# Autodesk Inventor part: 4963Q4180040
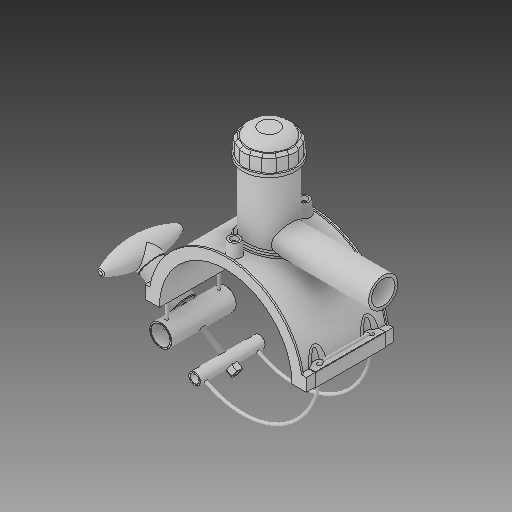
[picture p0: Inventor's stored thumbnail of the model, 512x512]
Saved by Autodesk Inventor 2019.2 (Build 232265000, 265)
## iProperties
Created: 2017-07
Part Number: 4963Q4180040
Material: Generic
Description: PLASSON TAPPING SADDLE 180x40
Document SubType Name: Modeling
Designer: KIM
Mass: 1712.7 g
Surface Area: 2671.49 cm^2
Volume: 1712.7 cm^3
Density: 1 g/cm^3
Appearance: Default
Author: KIM
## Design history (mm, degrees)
derived "4963Q4 (new clamping).ipt"
feature "Solid1::4963Q4 (new clamping).ipt"
feature "Solid2::4963Q4 (new clamping).ipt"
feature "Solid4::4963Q4 (new clamping).ipt"
feature "Solid5::4963Q4 (new clamping).ipt"
feature "Solid6::4963Q4 (new clamping).ipt"
feature "Solid7::4963Q4 (new clamping).ipt"
feature "Solid8::4963Q4 (new clamping).ipt"
feature "Solid9::4963Q4 (new clamping).ipt" dims "d70" = 15
feature "Solid10::4963Q4 (new clamping).ipt"
tag "TaggingFeature1"
body "Solid1"
body "Solid2"
body "Solid3"
body "Solid4"
body "Solid5"
body "Solid6"
body "Solid7"
other parameters: "d2" = 219, "d4" = 118, "d5" = 0, "d6" = 0.1, "d8" = 0, "d19" = 6, "d20" = 6, "d21" = 70.8, "d23" = 0, "d24" = 35.4, "d40" = 106.704, "d41" = 72, "d43" = 0, "d45" = 0, "d47" = 173.4, "d72" = 0, "d73" = 6, "d77" = 9, "d79" = 15, "d80" = 47.2, "d82" = 5 deg, "d84" = 4, "d85" = 14, "d86" = 0, "d87" = 3, "d88" = 0, "d89" = 1, "d90" = 1, "d91" = 94.4, "d92" = 0, "d93" = 0.5, "d94" = 94.73684, "d96" = 209.304, "d97" = 2.36, "d98" = 0, "d102" = 1.8, "d120" = 140 deg, "d121" = 24.228, "d122" = 20 deg, "d123" = 410.4, "d124" = 123.12, "d126" = 0, "d143" = 185.4, "d145" = 19.38462, "d149" = 2.7, "d150" = 21.32308, "d153" = 118, "d154" = 0, "d156" = 102.6, "d157" = 160 deg, "d159" = 5.04, "d161" = 2.7, "d162" = 70.8, "d163" = 0, "d167" = 18, "d168" = 100.09756, "d170" = 3.75, "d172" = 0, "d173" = 1, "d176" = 20 deg, "d177" = 12.6, "d178" = 25.2, "d180" = 0, "d183" = 10.08, "d184" = 10.08, "d185" = 38.35, "d186" = 38.35, "d187" = 102.6, "d188" = 7.56, "d189" = 12.6, "d190" = 0, "d191" = 153.9, "d193" = 7, "d194" = 4.13, "d195" = 90 deg, "d197" = 0, "d199" = 0, "d200" = 12.6, "d203" = 138, "d204" = 68.4, "d205" = 50.4, "d206" = 61.2, "d207" = 103.5, "d208" = 107.64, "d209" = 128.34, "d210" = 61.92, "d211" = 72, "d212" = 57.6, "d213" = 0.9, "d216" = 0, "d217" = 18, "d218" = 18, "d219" = 3.6, "d224" = 0, "d230" = 3.6, "d245" = 35.4, "d246" = 35.4, "d247" = 6, "d248" = 6, "d257" = 111, "d258" = 155, "d259" = 32, "d263" = 219, "d265" = 0, "d267" = 13.00006, "d268" = 2.60001, "d269" = 2.60001, "d271" = 2.60001, "d273" = 0, "d274" = 23.56194, "d275" = 144, "d277" = 72, "d278" = 288, "d280" = 0, "d283" = 0, "d285" = 0, "d286" = 17.5, "d287" = 17.5, "d289" = 0, "d290" = 1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
